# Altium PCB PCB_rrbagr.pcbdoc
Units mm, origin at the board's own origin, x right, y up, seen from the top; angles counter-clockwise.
Board outline 111.63 x 77.85 mm, 2 copper layers (Top Layer, Bottom Layer); 8 components, 13 nets, 76 pads, 0 vias.
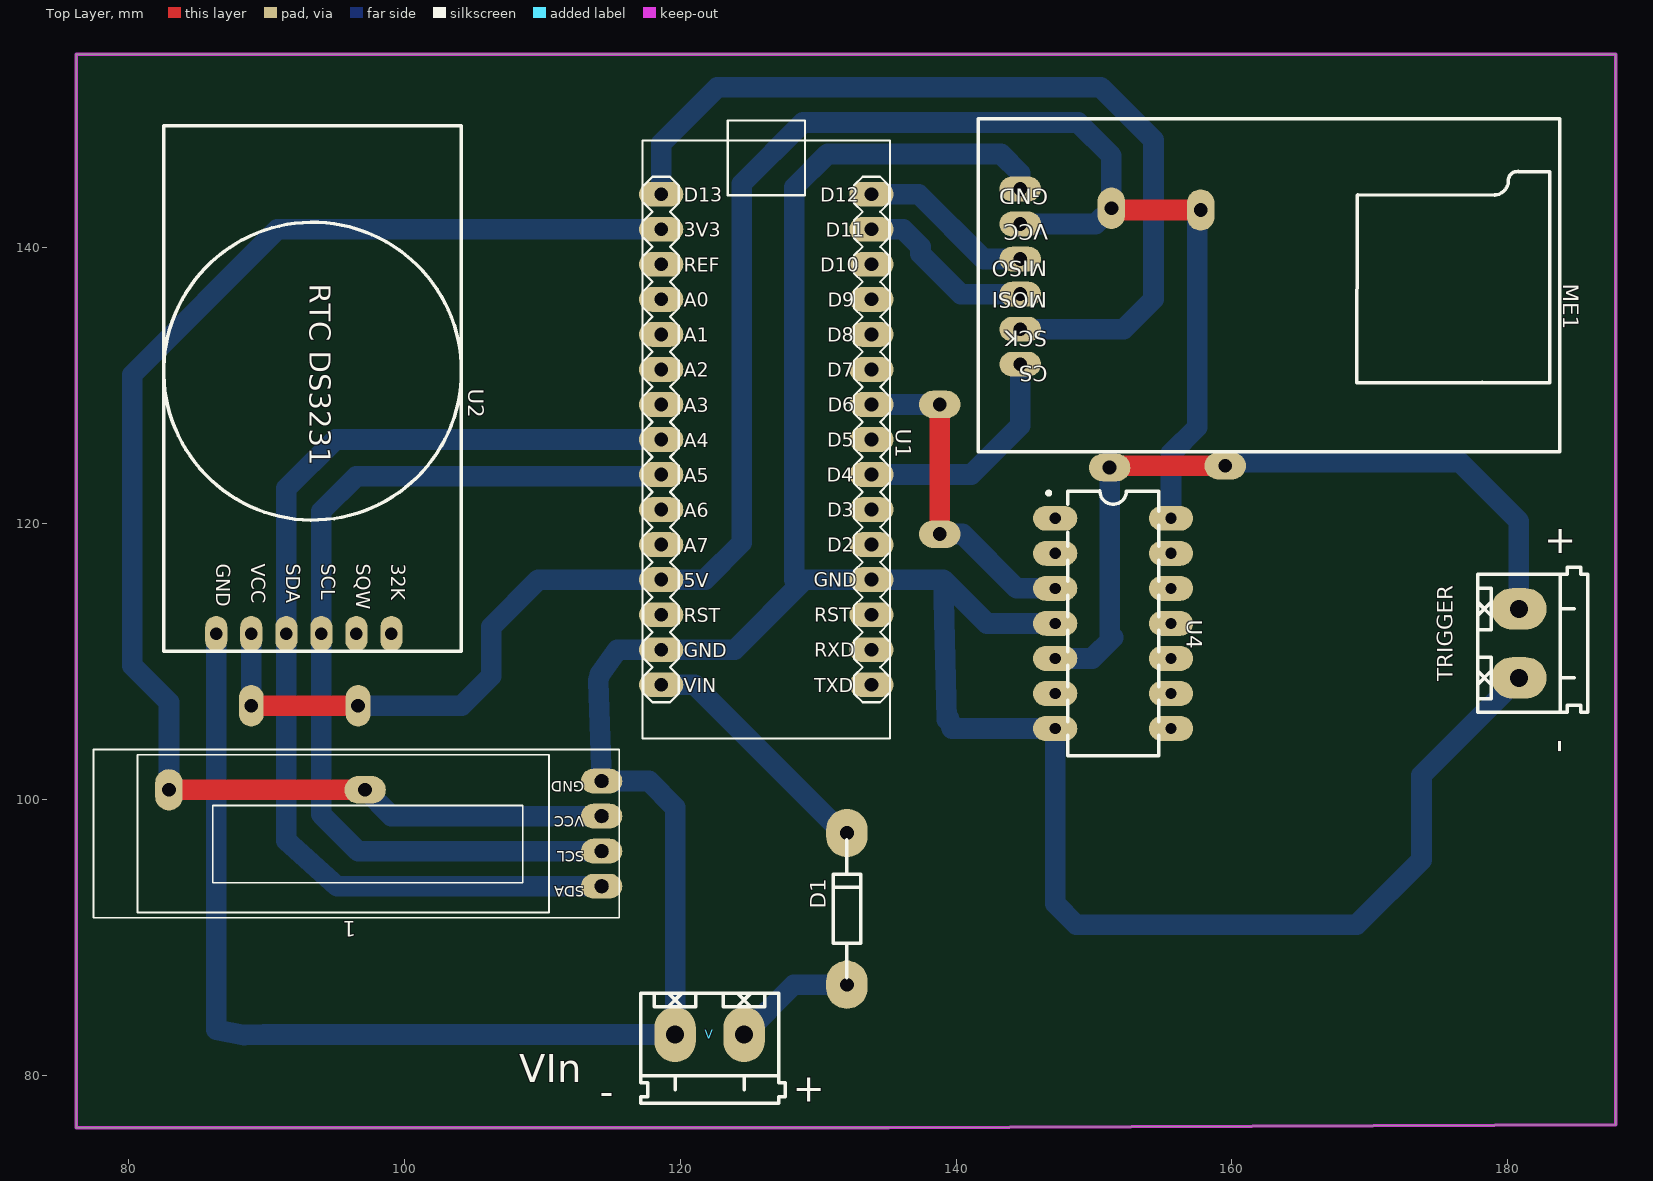
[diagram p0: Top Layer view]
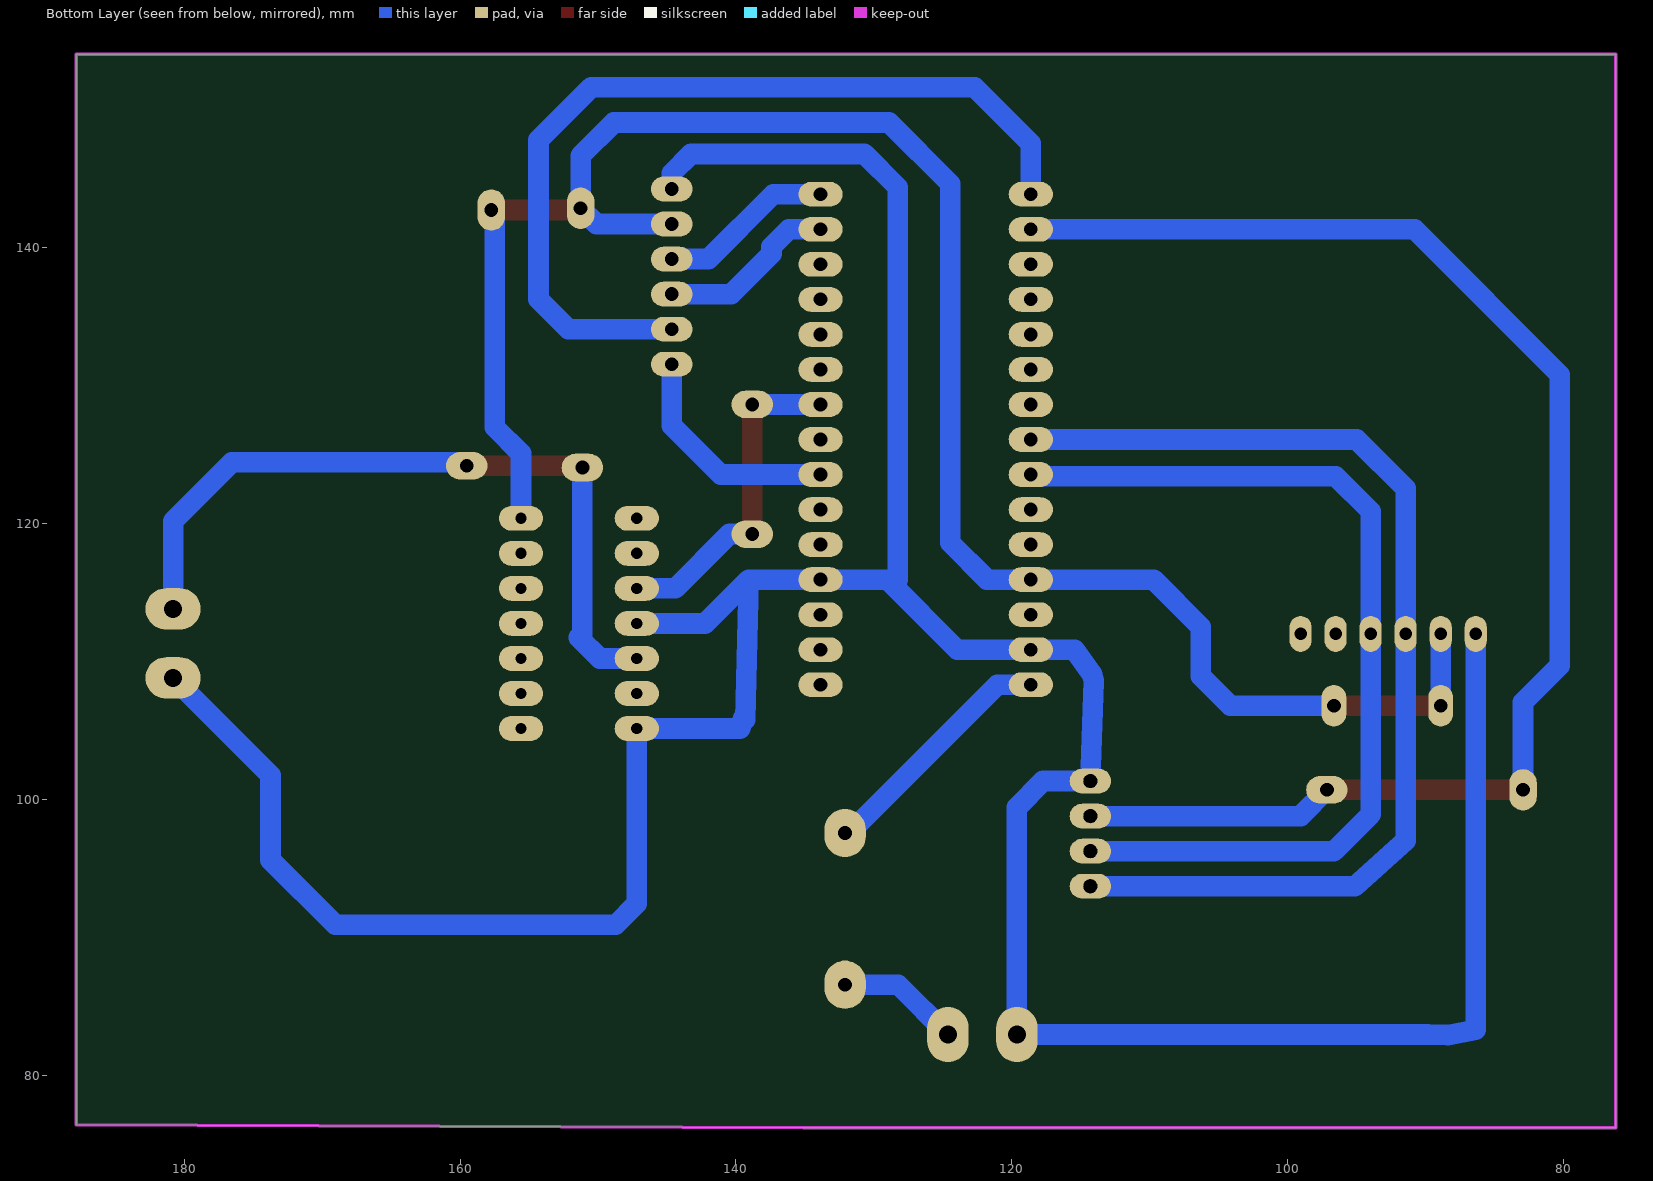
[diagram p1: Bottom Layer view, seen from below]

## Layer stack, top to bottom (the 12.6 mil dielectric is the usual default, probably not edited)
Top Layer: signal copper (thickness not stored)
Dielectric: dielectric 0.32, FR-4, Dk 4.8
Bottom Layer: signal copper (thickness not stored)

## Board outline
76.2,148.209 76.2,150.749 76.2,154.051 187.833,154.051 187.833,76.441 135.128,76.2 76.2,76.2 76.2,150.749 76.2,149.606

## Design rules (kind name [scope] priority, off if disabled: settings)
BoardOutlineClearance Default [All] p0: genericclearance=0.254 ignorepadtopadclearanceinfootprint=FALSE except(0: Region-CutoutEdge Arc-SplitContinuation Track-SplitContinuation SMDPad-SplitContinuation THPad-SplitContinuation Via-SplitContinuation Fill-SplitContinuation Poly-SplitContinuation Region-SplitContinuation Text-SplitContinuation; 0.249: Track-OutlineEdge SMDPad-OutlineEdge THPad-OutlineEdge Via-OutlineEdge Fill-OutlineEdge Region-OutlineEdge Poly-OutlineEdge Text-OutlineEdge Sheet-OutlineEdge Hole-OutlineEdge Track-CutoutEdge SMDPad-CutoutEdge THPad-CutoutEdge Via-CutoutEdge Fill-CutoutEdge Poly-CutoutEdge Text-CutoutEdge Sheet-CutoutEdge Hole-CutoutEdge)
Clearance Default [All] p1: gap=0.178 ignorepadtopadclearanceinfootprint=FALSE except(0: Region-Region; 0.249: Track-Track SMDPad-Track THPad-Track Via-Track Fill-Track Region-Track Poly-Track Text-Track Sheet-Track Hole-Track Track-SMDPad SMDPad-SMDPad THPad-SMDPad Via-SMDPad Fill-SMDPad Region-SMDPad Poly-SMDPad Text-SMDPad Sheet-SMDPad Hole-SMDPad Track-THPad SMDPad-THPad THPad-THPad Via-THPad Fill-THPad Region-THPad Poly-THPad Text-THPad Sheet-THPad Hole-THPad Track-Via SMDPad-Via THPad-Via Via-Via Fill-Via Region-Via Poly-Via Text-Via Sheet-Via Hole-Via Track-Fill SMDPad-Fill THPad-Fill Via-Fill Fill-Fill Region-Fill Poly-Fill Text-Fill Sheet-Fill Hole-Fill Track-Region SMDPad-Region THPad-Region Via-Region Fill-Region Poly-Region Text-Region Sheet-Region Hole-Region Track-Poly SMDPad-Poly THPad-Poly Via-Poly Fill-Poly Region-Poly Poly-Poly Text-Poly Sheet-Poly Hole-Poly Track-Text SMDPad-Text THPad-Text Via-Text Fill-Text Region-Text Poly-Text Text-Text Sheet-Text Hole-Text Track-Sheet SMDPad-Sheet THPad-Sheet Via-Sheet Fill-Sheet Region-Sheet Poly-Sheet Text-Sheet Sheet-Sheet Hole-Sheet Track-Hole SMDPad-Hole THPad-Hole Via-Hole Fill-Hole Region-Hole Poly-Hole Text-Hole Sheet-Hole Hole-Hole)
PasteMaskExpansion Common [All] p1: expansion=0
PlaneConnect Default [All] p1: planeconnectstyle=Relief reliefexpansion=0.508 reliefentries=4 reliefconductorwidth=0 reliefairgap=0.025
PolygonConnect Default [All] p1: connectstyle=Relief reliefentries=4 reliefconductorwidth=0 polygonreliefangle="90 Angle" airgapwidth=10
RoutingVias Default [All] p1: viastyle="Through Hole" holewidth=12.008000000000001 minholewidth=12.008000000000001 maxholewidth=2362 width=24.016000000000002 minwidth=24.016000000000002 maxwidth=3938
SolderMaskExpansion Common [All] p1: useseparateexpansions=TRUE expansion=2 expansionbottom=2
Width Default [All] p1: maxlimit=1000 minlimit=59 preferedwidth=59

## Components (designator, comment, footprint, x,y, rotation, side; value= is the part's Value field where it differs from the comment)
1 "0.91” 128X32 OLED" DISPLAY-OLED-128X32 96.52,97.536 r180 top
D1 "DIODE_1N4007" DIODE_1N4007 132.08,92.583 r90 top
ME1 "CATALEX_MICRO_SD_CARD_MODULE_V1" MICRO_SD_CARD_MODULE_V1 141.605,149.352 r270 top
TRIGGER "triggger" "M02 SCREW TERMINAL 5MM 10X8MM" 185.801,116.332 r180 top
U1 "ARDUINO_NANO" COMM-TH_ARDUINO_NANO 126.238,126.111 r270 top
U2 "Connector for the RTC DS3231" DS3231-RTC-MODULE 82.55,110.744 r270 top
U4 "CD4066BE" DIP-14_L19.2-W6.6-P2.54-LS10.9-BL 151.384,112.776 r270 top
V "Battery" "M02 SCREW TERMINAL 5MM 10X8MM" 127.127,77.978 r90 top

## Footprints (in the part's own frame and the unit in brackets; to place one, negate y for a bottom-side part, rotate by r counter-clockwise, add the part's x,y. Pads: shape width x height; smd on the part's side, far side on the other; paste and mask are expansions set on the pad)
COMM-TH_ARDUINO_NANO [mm]
  oval 1.8x3.2 hole 1: 1(17.78,7.62) 2(15.24,7.62) 3(12.7,7.62) 4(10.16,7.62) 5(7.62,7.62) 6(5.08,7.62) 7(2.54,7.62) 8(0,7.62) 9(-2.54,7.62) 10(-5.08,7.62) 11(-7.62,7.62) 12(-10.16,7.62) 13(-12.7,7.62) 14(-15.24,7.62) 15(-17.78,7.62) 16(-17.78,-7.62) 17(-15.24,-7.62) 18(-12.7,-7.62) 19(-10.16,-7.62) 20(-7.62,-7.62) 21(-5.08,-7.62) 22(-2.54,-7.62) 23(0,-7.62) 24(2.54,-7.62) 25(5.08,-7.62) 26(7.62,-7.62) 27(10.16,-7.62) 28(12.7,-7.62) 29(15.24,-7.62) 30(17.78,-7.62)
  silkscreen extent -23.11,-8.97 21.67,8.97
DIODE_1N4007 [mm]
  oval 3.5x3 hole 1: 1(-6,0) 2(5,0)
  silkscreen extent -5.5,-1 4.5,1
DIP-14_L19.2-W6.6-P2.54-LS10.9-BL [mm]
  oval 1.8x3.2 hole 0.813: 1(-7.62,-4.2) 2(-5.08,-4.2) 3(-2.54,-4.2) 4(0,-4.2) 5(2.54,-4.2) 6(5.08,-4.2) 7(7.62,-4.2) 8(7.62,4.2) 9(5.08,4.2) 10(2.54,4.2) 11(0,4.2) 12(-2.54,4.2) 13(-5.08,4.2) 14(-7.62,4.2)
  silkscreen extent -9.6,-4.8 9.6,3.3
DISPLAY-OLED-128X32 [mm]
  oval 3x1.8 hole 1: 1(-17.78,-3.81) 2(-17.78,-1.27) 3(-17.78,1.27) 4(-17.78,3.81)
  silkscreen extent -19.05,-6.1 19.05,6.1
DS3231-RTC-MODULE [mm]
  oval 2.6x1.6 hole 0.914: 1(-1.27,16.51) 2(-1.27,13.97) 3(-1.27,11.43) 4(-1.27,8.89) 5(-1.27,6.35) 6(-1.27,3.81)
  silkscreen extent -38.1,0 0,21.59
"M02 SCREW TERMINAL 5MM 10X8MM" [mm]
  oval 4x3 hole 1.3: 1(5,7.5) 2(5,2.5)
  silkscreen extent 0,-0.5 8,10
MICRO_SD_CARD_MODULE_V1 [mm]
  oval 1.8x3 hole 1: 1(5.083,3.048) 2(7.623,3.048) 3(10.163,3.048) 4(12.703,3.048) 5(15.243,3.048) 6(17.783,3.048)
  silkscreen extent 0,0 24.13,42.16

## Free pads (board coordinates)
  oval 1.8x3 hole 1: 3(88.9,106.807) 4(96.647,106.807)
  oval 3x2 hole 1: 7(97.155,100.711) 12(138.811,119.253) 13(138.811,128.651) 14(151.13,124.079) 15(159.512,124.206)
  oval 2x3 hole 1: 9(82.931,100.711) 10(151.257,142.875) 11(157.734,142.748)

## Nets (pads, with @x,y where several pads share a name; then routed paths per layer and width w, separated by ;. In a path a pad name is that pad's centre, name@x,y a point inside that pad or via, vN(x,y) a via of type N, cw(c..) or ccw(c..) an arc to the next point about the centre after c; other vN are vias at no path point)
3.3: 1.2 pad.7 pad.9 U1.17 | length 106.1
  Top Layer w1.5: pad.9 pad.7
  Bottom Layer w1.5: pad.9 82.931,107.061 80.264,109.728 80.264,130.81 90.805,141.351 U1.17 ; pad.7 99.06,98.806 1.2
4: pad.12 pad.13 U1.9 U4.3 | length 24.4
  Top Layer w1.5: pad.12 pad.13
  Bottom Layer w1.5: U1.9 pad.13 ; pad.12 140.462,119.253 144.399,115.316 U4.3
CS: ME1.6 U1.7 | length 16.7
  Bottom Layer w1.5: U1.7 141.097,123.571 144.653,127.127 ME1.6
GND: 1.1 ME1.1 TRIGGER.1 U1.4 U1.29 U2.6 U4.4 U4.7 V.1 | length 257.6
  Bottom Layer w1.5: U2.6 86.36,83.312 88.392,82.931 89.836,82.978 V.1 ; V.1@119.626,82.979 119.626,99.433 117.729,101.346 1.1 114.046,108.585 114.173,109.093 115.443,110.871 U1.29 123.952,110.871 129.032,115.951 ; 139.319,105.791 139.065,115.951 ; 139.446,105.918 139.7,105.156 U4.7 147.184,92.465 148.717,90.932 169.037,90.932 173.736,95.631 173.736,101.767 TRIGGER.1 ; 141.336,113.68 139.065,115.951 ; ME1.1 144.653,145.415 143.256,146.812 130.683,146.812 128.27,144.399 128.27,115.951 129.032,115.951 ; U4.4 142.24,112.776 139.065,115.951 ; 129.032,115.951 U1.4 139.065,115.951
MISO: ME1.3 U1.15 | length 12.7
  Bottom Layer w1.5: U1.15 137.287,143.891 141.989,139.189 ME1.3
MOSI: ME1.4 U1.14 | length 13
  Bottom Layer w1.5: U1.14 136.144,141.351 137.414,140.081 137.414,139.573 140.338,136.649 ME1.4
SCK: ME1.5 U1.16 | length 64.7
  Bottom Layer w1.5: U1.16 118.618,147.574 122.682,151.638 150.495,151.638 154.305,147.828 154.305,136.271 152.143,134.109 ME1.5
SCL: 1.3 U1.24 U2.3 | length 69
  Bottom Layer w1.5: 1.3 96.647,96.266 93.98,98.933 U2.3 93.98,120.904 96.52,123.444 U1.24@118.491,123.444
SDA: 1.4 U1.23 U2.4 | length 78.3
  Bottom Layer w1.5: 1.4 95.25,93.726 95.123,93.726 91.44,97.028 U2.4 91.44,122.555 94.996,126.111 U1.23
T3_2: D1.1 V.2 | length 8.9
  Bottom Layer w1.5: V.2 128.232,86.583 D1.1
U4_5: pad.14 pad.15 TRIGGER.2 U4.5 | length 55.2
  Top Layer w1.5: pad.14 151.257,124.206 pad.15
  Bottom Layer w1.5: U4.5 149.86,110.236 151.384,111.76 151.13,112.014 pad.14 ; pad.15 159.766,124.46 176.53,124.46 180.801,120.189 TRIGGER.2
U5_4: D1.2 U1.30 | length 17.9
  Bottom Layer w1.5: U1.30 121.031,108.331 131.779,97.583 D1.2
VCC: ME1.2 pad.3 pad.4 pad.10 pad.11 U1.27 U2.5 U4.14 | length 144.1
  Top Layer w1.5: pad.3 pad.4 ; pad.10 151.384,142.748 pad.11
  Bottom Layer w1.5: pad.3 U2.5 ; pad.4 104.14,106.807 106.299,108.966 106.299,112.522 109.728,115.951 U1.27 121.793,115.951 124.46,118.618 124.46,144.653 128.905,149.098 148.844,149.098 151.257,146.685 pad.10 150.111,141.729 ME1.2 ; U4.14 155.584,125.104 157.48,127 157.48,142.494 pad.11
pads on no net: U1.1 U1.2 U1.3 U1.5 U1.6 U1.8 U1.10 U1.11 U1.12 U1.13 U1.18 U1.19 U1.20 U1.21 U1.22 U1.25 U1.26 U1.28 U2.1 U2.2 U4.1 U4.2 U4.6 U4.8 U4.9 U4.10 U4.11 U4.12 U4.13

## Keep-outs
Board Outline Layer:
  lines w0.254: 76.2,148.209 76.2,150.749 ; 76.2,149.606 76.2,150.749 ; 76.2,150.749 76.2,154.051 187.833,154.051 187.833,76.441 135.128,76.2 76.2,76.2 76.2,150.749

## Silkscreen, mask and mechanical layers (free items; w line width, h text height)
Top Silkscreen Layer:
  text "+" at 182.626,117.856 h2.03
  text "-" at 184.531,103.378 h2.03 r90
  text "VIn" at 108.331,79.502 h2.03
  text "+" at 128.143,78.105 h2.03
  text "-" at 114.173,77.851 h2.03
